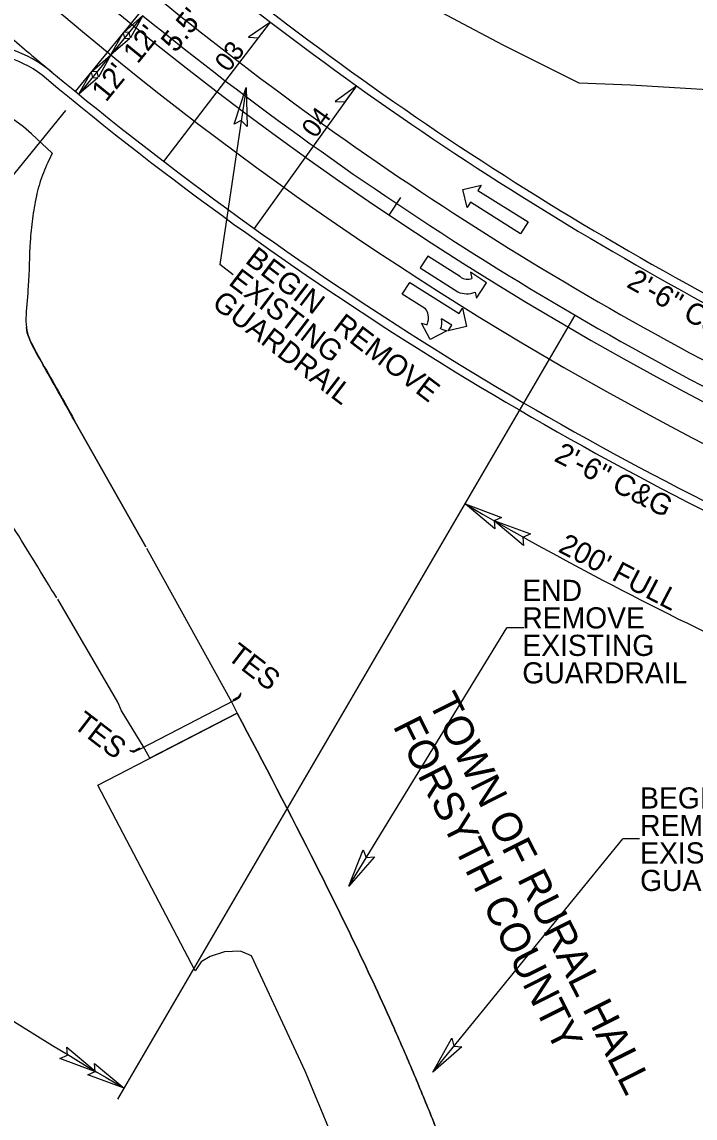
# Model space of a CAD drawing. Extents: x 1616561 to 1622460, y 896726 to 899651.
# Drawn here: x 1619267.2 to 1619426.3, y 897963.2 to 898222.4 of the extents above; entities that cross this region are included whole.
import ezdxf

# ---------------------------------------------------------------- set-up
doc = ezdxf.new("R2010")
doc.units = 0
for name, color, linetype in [('Old_Level_3', 7, 'Continuous'), ('Prop Conc Curb and Gutter', 7, 'Continuous'), ('Prop Dimension', 7, 'Continuous'), ('Prop DSN Text', 7, 'Continuous'), ('Prop Guardrail', 7, 'Continuous'), ('Prop Guardrail Anchor Unit CELL', 7, 'Continuous'), ('Prop Horizontal Alignment Tick Small', 7, 'Continuous'), ('Prop Lane Arrow CELL', 7, 'Continuous'), ('Prop North Arrow NAD83 for Plan Sheets CELL', 7, 'Continuous'), ('Prop Rem of Exist Asph Pvmt', 7, 'Continuous'), ('Prop Superelevation  Arrow CELL', 7, 'Continuous'), ('Prop Terminator CELL', 7, 'Continuous'), ('Sheet Cutting Line CELL', 7, 'Continuous'), ('Sheet Sticker Preliminary CELL', 7, 'Continuous')]:
    doc.layers.add(name, color=color, linetype=linetype)

msp = doc.modelspace()

# ---------------------------------------------------------------- linework, layer by layer
at = {"layer": 'Old_Level_3'}
for radius, start, end in [(791.25, 230.78618, 245.11013), (808.75, 229.34838, 255.58792), (796.75, 230.7866, 245.11013), (820.75, 229.34838, 230.21163)]:
    msp.add_arc((1619799.51, 898841.24), radius, start, end, dxfattribs=at)
at = {"layer": 'Prop Conc Curb and Gutter'}
for p, q in [((1619285.14, 898041.92), (1619318.09, 898059)), ((1619308.11, 897998.05), (1619285.14, 898041.92)), ((1619334.15, 897974.32), (1619321.42, 898001.61))]:
    msp.add_line(p, q, dxfattribs=at)
msp.add_lwpolyline([(1619321.42, 898001.61), (1619318.85, 898002.66), (1619315.11, 898002.5), (1619311.68, 898001.42), (1619309.55, 898000.14), (1619308.11, 897998.05)], dxfattribs=at)
for points in [[(1619318.09, 898059), (1619336.73, 898023.03), (1619355.17, 897984.46), (1619359.66, 897974.11), (1619363.95, 897963.69), (1619368.1, 897953.21), (1619372.13, 897942.68), (1619375.39, 897934.08), (1619378.62, 897925.47), (1619384.71, 897908.13)], [(1619371.66, 897871.04), (1619364.15, 897895.46), (1619350.2, 897934.66), (1619334.15, 897974.32)]]:
    msp.add_spline(points, degree=3, dxfattribs=at)
at = {"layer": 'Prop Dimension'}
for p, q in [((1619295.8, 898223.93), (1619288.21, 898214.63)), ((1619288.21, 898214.63), (1619280.62, 898205.33)), ((1619277.46, 898201.46), (1619160.12, 898057.65)), ((1619289.85, 897967.7), (1619398, 898153.06))]:
    msp.add_line(p, q, dxfattribs=at)
for radius, start, end in [(848.4, 239.73865, 245.11013), (1008.36, 230.78618, 239.73865)]:
    msp.add_arc((1619799.51, 898841.24), radius, start, end, dxfattribs=at)
at = {"layer": 'Prop DSN Text'}
for p, q in [((1619320.18, 898206.92), (1619313.99, 898165.06)), ((1619317.14, 898162.64), (1619313.99, 898165.06)), ((1619344.48, 898018.1), (1619381.84, 898079.14)), ((1619385.82, 898079.14), (1619381.84, 898079.14)), ((1619364.32, 897974.1), (1619409.21, 898029.22)), ((1619413.19, 898029.22), (1619409.21, 898029.22))]:
    msp.add_line(p, q, dxfattribs=at)
at = {"layer": 'Prop Guardrail'}
msp.add_line((1619317.33, 898061.98), (1619295.13, 898050.48), dxfattribs=at)
at = {"layer": 'Prop Guardrail Anchor Unit CELL'}
for p, q in [((1619317.2, 898062.23), (1619318.2, 898062.75)), ((1619317.33, 898061.98), (1619318.33, 898062.5)), ((1619317.33, 898061.98), (1619317.2, 898062.23)), ((1619295, 898050.72), (1619294, 898050.21)), ((1619295.13, 898050.48), (1619294.13, 898049.96)), ((1619295.13, 898050.48), (1619295, 898050.72))]:
    msp.add_line(p, q, dxfattribs=at)
for centre, radius, start, end in [((1619317.39, 898064.13), 1.6, 300.2149, 348.5223), ((1619317.71, 898063.6), 1.27, 299.0683, 9.4623), ((1619293.34, 898051.66), 1.6, 246.2725, 294.5799), ((1619293.58, 898051.1), 1.27, 225.3325, 295.7265)]:
    msp.add_arc(centre, radius, start, end, dxfattribs=at)
at = {"layer": 'Prop Horizontal Alignment Tick Small'}
for centre, radius, start, end in [((1619799.51, 898841.24), 777.25, 229.34838, 244.13867), ((1619255.07, 898187.51), 28, 50.2116, 133.0475), ((1619799.51, 898841.24), 822.75, 230.21163, 245.81358)]:
    msp.add_arc(centre, radius, start, end, dxfattribs=at)
at = {"layer": 'Prop Lane Arrow CELL'}
for p, q in [((1619371.41, 898182.84), (1619375.78, 898183.88)), ((1619372.43, 898178.54), (1619371.41, 898182.84)), ((1619375.78, 898183.88), (1619374.98, 898182.61)), ((1619374.98, 898182.61), (1619386.84, 898175.16)), ((1619373.23, 898179.81), (1619372.43, 898178.54)), ((1619385.08, 898172.37), (1619373.23, 898179.81)), ((1619386.84, 898175.16), (1619385.08, 898172.37)), ((1619363.13, 898167.05), (1619361.36, 898164.26)), ((1619370.85, 898162.15), (1619363.13, 898167.05)), ((1619361.36, 898164.26), (1619370.27, 898158.61)), ((1619357.09, 898158.04), (1619358.85, 898160.84)), ((1619358.85, 898160.84), (1619370.54, 898153.5)), ((1619377.03, 898160.77), (1619373.26, 898163.23)), ((1619373.26, 898163.23), (1619373.58, 898161.78)), ((1619374.63, 898157.08), (1619377.03, 898160.77)), ((1619374.3, 898158.53), (1619374.63, 898157.08)), ((1619362.56, 898154.61), (1619357.09, 898158.04)), ((1619370.54, 898153.5), (1619371.33, 898154.77)), ((1619371.33, 898154.77), (1619372.28, 898150.45)), ((1619363.71, 898147.33), (1619361.62, 898151.24)), ((1619361.62, 898151.24), (1619363.02, 898150.84)), ((1619368.78, 898150.7), (1619366.37, 898152.22)), ((1619367.98, 898149.43), (1619368.78, 898150.7)), ((1619372.28, 898150.45), (1619367.98, 898149.43)), ((1619367.62, 898149.42), (1619363.71, 898147.33)), ((1619366.18, 898149.85), (1619367.62, 898149.42))]:
    msp.add_line(p, q, dxfattribs=at)
for centre, radius, start, end in [((1619372.61, 898164.89), 3.28, 237.592, 287.2502), ((1619372.37, 898163.4), 5.25, 246.2681, 291.5798), ((1619360.72, 898152.88), 2.52, 6.9459, 43.2579), ((1619358.86, 898152.38), 4.43, 339.5824, 10.436), ((1619362.02, 898151.41), 4.43, 339.4636, 10.3422)]:
    msp.add_arc(centre, radius, start, end, dxfattribs=at)
at = {"layer": 'Prop North Arrow NAD83 for Plan Sheets CELL'}
for points in [[(1619325.96, 898222.39), (1619320.73, 898218.84), (1619323.15, 898218.71)], [(1619346.32, 898207.32), (1619341.21, 898203.61), (1619343.63, 898203.56)]]:
    msp.add_lwpolyline(points, close=True, dxfattribs=at)
at = {"layer": 'Prop Rem of Exist Asph Pvmt'}
for p, q in [((1619380.93, 898216.97), (1619348.44, 898234.23)), ((1619398.89, 898207.97), (1619380.93, 898216.97)), ((1619269.47, 898196.01), (1619274.36, 898191.44)), ((1619296.62, 898097.96), (1619316.73, 898061.63)), ((1619316.73, 898061.63), (1619318.09, 898059)), ((1619290.89, 898059.28), (1619290.74, 898059.55)), ((1619295.81, 898051.15), (1619290.89, 898059.28)), ((1619318.09, 898059), (1619297.45, 898048.3)), ((1619297.45, 898048.3), (1619295.81, 898051.15))]:
    msp.add_line(p, q, dxfattribs=at)
for points in [[(1619515.06, 898201.52), (1619491.31, 898202.8), (1619473.44, 898203.85), (1619442.37, 898205.63), (1619411.08, 898207.46), (1619398.89, 898207.97)], [(1619296.45, 898098.32), (1619280.03, 898127.41)], [(1619280.03, 898127.41), (1619296.45, 898098.32)], [(1619290.74, 898059.55), (1619289.87, 898061.58), (1619275.69, 898085.92)]]:
    msp.add_lwpolyline(points, dxfattribs=at)
msp.add_arc((1619248.97, 898174.11), 30, 46.8949, 122.2079, dxfattribs=at)
for points in [[(1619274.36, 898191.44), (1619274.11, 898190.92), (1619272.04, 898186.18), (1619270.59, 898181.28), (1619270.1, 898178.58), (1619269.67, 898175.89), (1619269.34, 898173.18), (1619269.13, 898170.47), (1619268.67, 898159.98), (1619268.17, 898153.14), (1619268.23, 898150.16), (1619268.87, 898147.73), (1619272.47, 898140.89), (1619280.03, 898127.41)], [(1619275.41, 898086.22), (1619265.12, 898102.96), (1619249.89, 898126.67), (1619236.73, 898147.21), (1619219.57, 898173.07)], [(1619280.03, 898127.41), (1619272.47, 898140.89), (1619270.63, 898144.28), (1619269.74, 898145.99), (1619268.87, 898147.73), (1619268.23, 898150.16), (1619268.22, 898150.3)]]:
    msp.add_spline(points, degree=3, dxfattribs=at)
at = {"layer": 'Prop Superelevation  Arrow CELL'}
msp.add_line((1619353.99, 898176.78), (1619356.77, 898180.93), dxfattribs=at)
at = {"layer": 'Prop Terminator CELL'}
for p, q in [((1619285.14, 898041.92), (1619318.09, 898059)), ((1619308.11, 897998.05), (1619285.14, 898041.92)), ((1619334.15, 897974.32), (1619321.42, 898001.61))]:
    msp.add_line(p, q, dxfattribs=at)
for points in [[(1619291.32, 898220.03), (1619295.8, 898223.93), (1619292.88, 898218.71), (1619292.55, 898219.95)], [(1619292.69, 898218.52), (1619288.21, 898214.63), (1619291.12, 898219.84), (1619291.46, 898218.61)], [(1619283.73, 898210.73), (1619288.21, 898214.63), (1619285.3, 898209.41), (1619284.96, 898210.65)], [(1619285.1, 898209.23), (1619280.62, 898205.33), (1619283.54, 898210.55), (1619283.87, 898209.31)], [(1619317.33, 898198.24), (1619320.18, 898206.92), (1619320.44, 898197.73), (1619319.02, 898199.1)], [(1619378.96, 898102.57), (1619371.97, 898108.45), (1619380.59, 898105.27), (1619378.79, 898104.46)], [(1619385.76, 898098.66), (1619378.77, 898104.54), (1619387.39, 898101.36), (1619385.59, 898100.55)], [(1619350.5, 898024.96), (1619344.48, 898018.1), (1619347.84, 898026.65), (1619348.6, 898024.83)], [(1619371.2, 897980.1), (1619364.32, 897974.1), (1619368.79, 897982.13), (1619369.31, 897980.22)], [(1619277.81, 897979.99), (1619284.8, 897974.11), (1619276.18, 897977.29), (1619277.98, 897978.09)], [(1619284.37, 897976.16), (1619291.36, 897970.29), (1619282.73, 897973.47), (1619284.53, 897974.27)]]:
    msp.add_lwpolyline(points, close=True, dxfattribs=at)
msp.add_lwpolyline([(1619321.42, 898001.61), (1619318.85, 898002.66), (1619315.11, 898002.5), (1619311.68, 898001.42), (1619309.55, 898000.14), (1619308.11, 897998.05)], dxfattribs=at)
for centre, radius, start, end in [((1619799.51, 898841.24), 779.25, 229.34838, 244.13867), ((1619255.07, 898187.51), 30, 50.2116, 133.0475), ((1619799.51, 898841.24), 820.75, 230.21163, 245.81358)]:
    msp.add_arc(centre, radius, start, end, dxfattribs=at)
for points in [[(1619384.71, 897908.13), (1619378.62, 897925.47), (1619375.39, 897934.08), (1619372.13, 897942.68), (1619368.1, 897953.21), (1619363.95, 897963.69), (1619359.66, 897974.11), (1619355.17, 897984.46), (1619336.73, 898023.03), (1619318.09, 898059)], [(1619371.66, 897871.04), (1619364.15, 897895.46), (1619350.2, 897934.66), (1619334.15, 897974.32)]]:
    msp.add_spline(points, degree=3, dxfattribs=at)
at = {"layer": 'Sheet Cutting Line CELL'}
msp.add_arc((1619799.51, 898841.24), 800, 229.34838, 270, dxfattribs=at)
at = {"layer": 'Sheet Sticker Preliminary CELL'}
for p, q in [((1619279.83, 898205.98), (1619306.1, 898238.1)), ((1619300.74, 898189.43), (1619325.96, 898222.39)), ((1619322.19, 898173.56), (1619346.32, 898207.32))]:
    msp.add_line(p, q, dxfattribs=at)

# ---------------------------------------------------------------- texts
at = {"layer": 'Prop Dimension'}
for s, height, rotation, p in [("5.5'", 5, 50.7862, (1619303.48, 898214.96)), ("12'", 5, 50.7862, (1619294.53, 898212.35)), ("12'", 5, 50.7862, (1619287.06, 898203.31)), ('2\'-6" C&G', 5.044, 330.6111, (1619409.86, 898159.91)), ('2\'-6" C&G', 5.044, 332.8822, (1619392.73, 898118.75)), ("200' FULL", 5, 332.3522, (1619393.7, 898097.27)), ('TES', 5, 322.4435, (1619315.43, 898071.96)), ('TES', 5, 322.4435, (1619279.05, 898055.79))]:
    msp.add_text(s, height=height, rotation=rotation, dxfattribs=at).set_placement(p)
at = {"layer": 'Prop DSN Text'}
for s, height, rotation, p in [('BEGIN ', 5, 322.663, (1619319.72, 898165.64)), ('EXISTING', 5, 322.663, (1619315.78, 898160.48)), ('GUARDRAIL', 5, 322.663, (1619311.83, 898155.31)), ('REMOVE', 5, 322.663, (1619340.42, 898149.85)), ('TOWN OF RURAL HALL', 7, 296.6541, (1619363.18, 898061.61)), ('FORSYTH COUNTY', 7, 296.6541, (1619354.8, 898055.95))]:
    msp.add_text(s, height=height, rotation=rotation, dxfattribs=at).set_placement(p)
for s, p in [('END', (1619385.48, 898085.51)), ('REMOVE', (1619385.48, 898079.01)), ('EXISTING', (1619385.48, 898072.51)), ('GUARDRAIL', (1619385.48, 898066.01)), ('BEGIN', (1619413.34, 898036.42)), ('REMOVE', (1619413.34, 898029.92)), ('EXISTING', (1619413.34, 898023.42)), ('GUARDRAIL', (1619413.34, 898016.92))]:
    msp.add_text(s, height=5, dxfattribs=at).set_placement(p)
at = {"layer": 'Sheet Sticker Preliminary CELL'}
for s, rotation, p in [('03', 52.4548, (1619315.98, 898210.34)), ('04', 54.3169, (1619336.61, 898194.72))]:
    msp.add_text(s, height=4.5, rotation=rotation, dxfattribs=at).set_placement(p)

doc.saveas('drawing.dxf')
